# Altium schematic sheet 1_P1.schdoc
size 604 x 431 mm; Symbol: sheet-symbol_a4; Device: Sheet-Symbol_A4; @Page Name: P1; @Create Date: 2023-08-18; @Page Count: 1; @Page No: 1; @Project Name: 【废土科技】带抬头显示及监控器的多功能观测仪_V3; @Schematic Name: 中控板; @Update Date: 2023-08-20; Company: 嘉立创EDA; Drawed: Kevin_Wuu; Page Size: A4; Version: V1.0
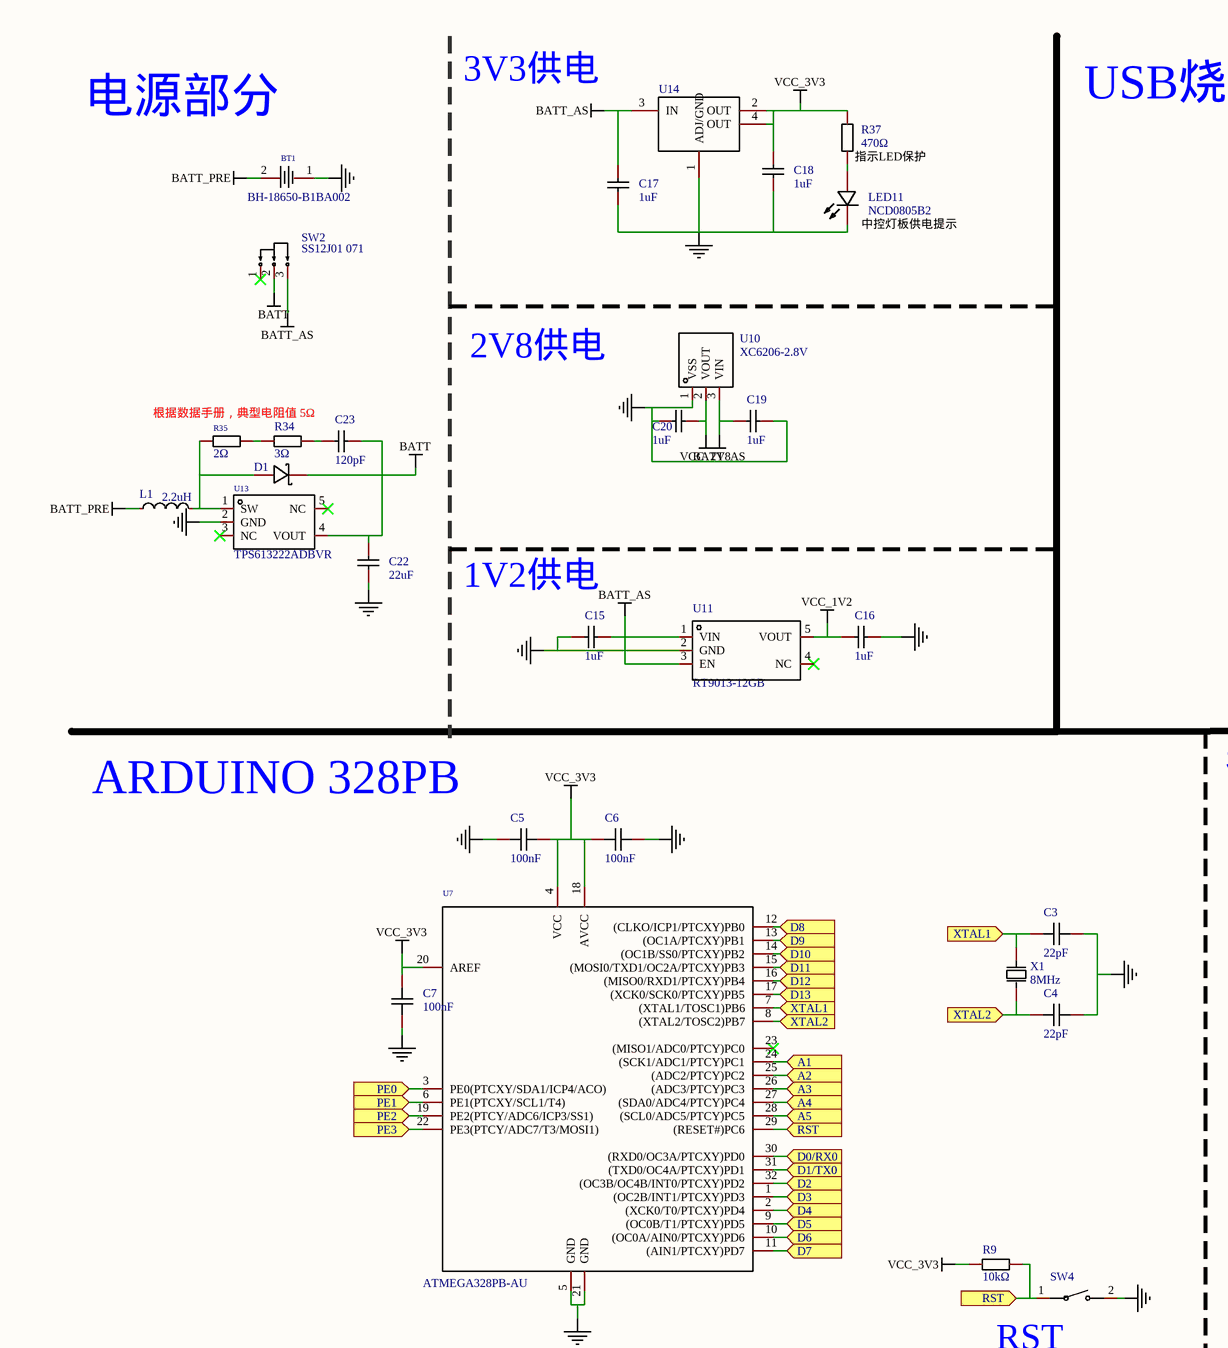
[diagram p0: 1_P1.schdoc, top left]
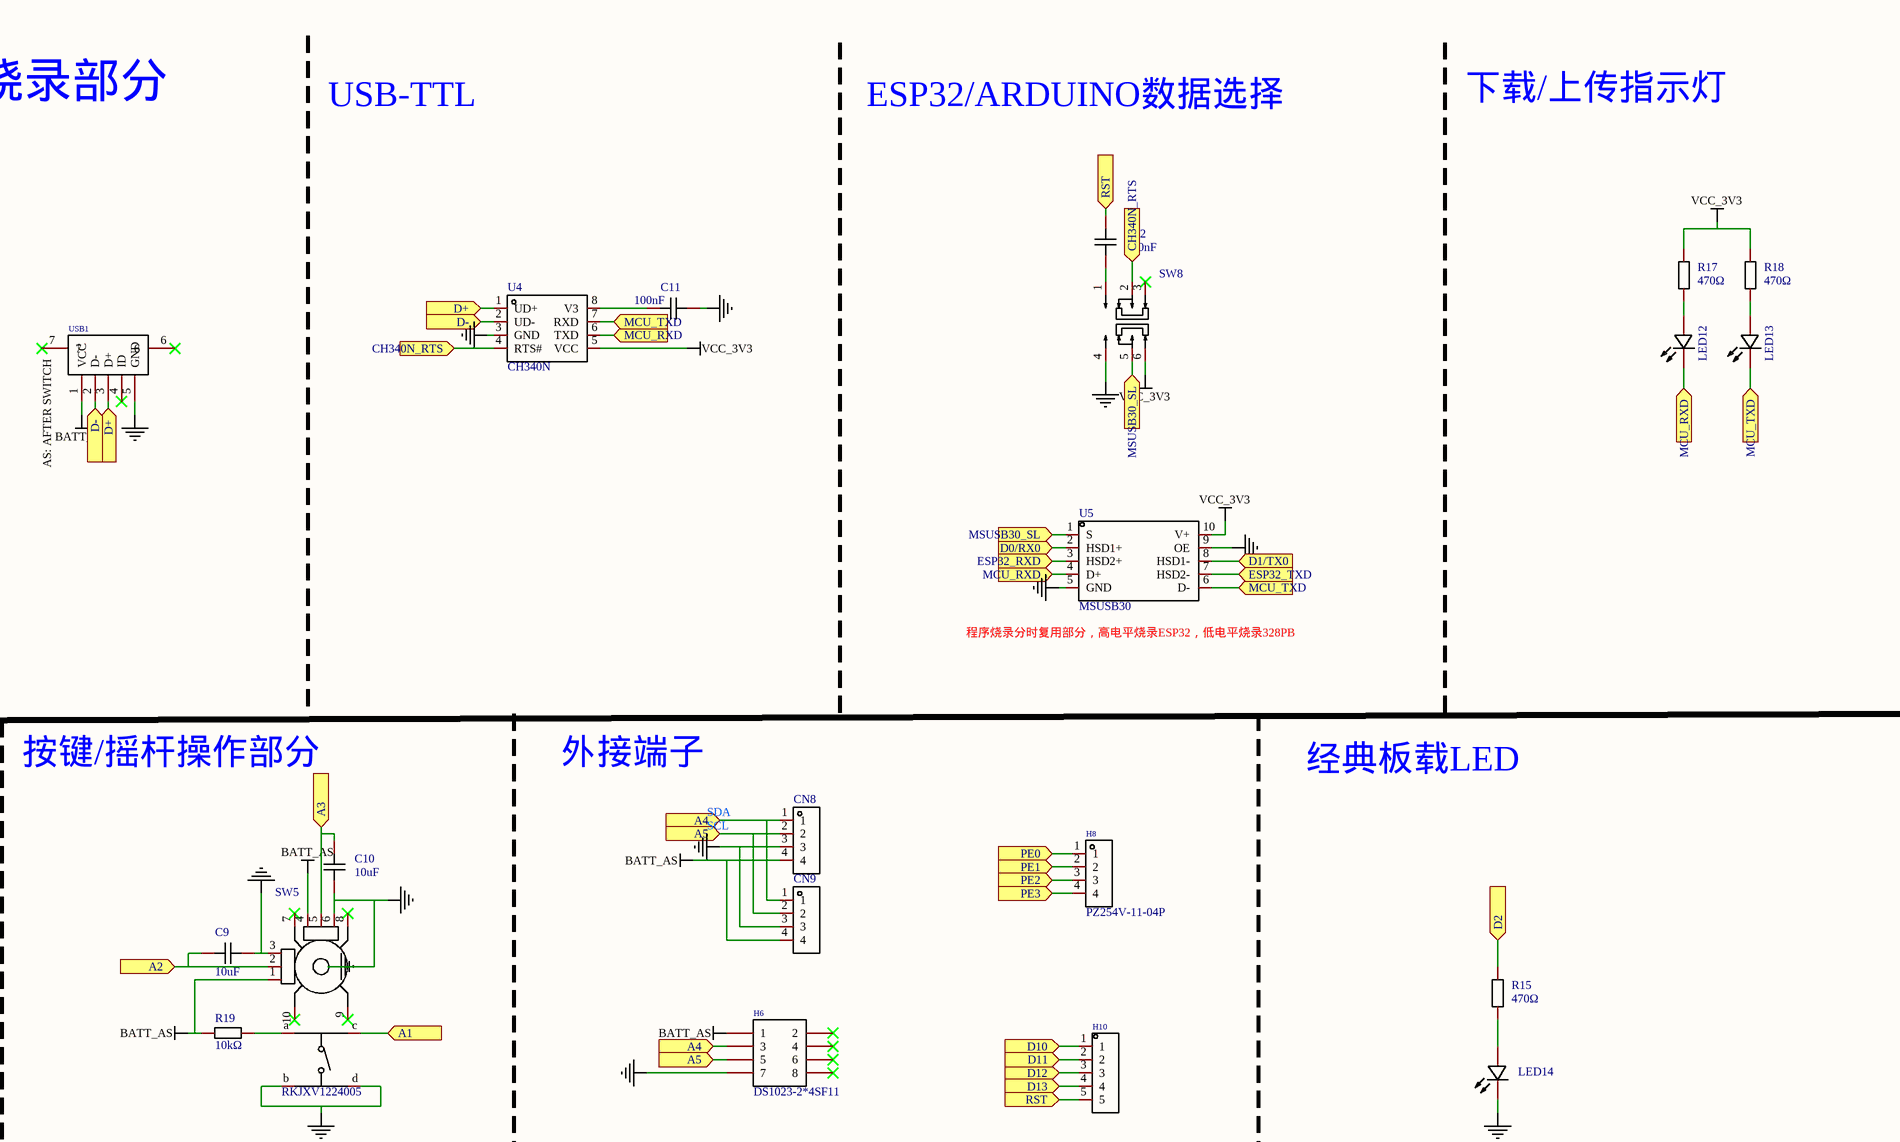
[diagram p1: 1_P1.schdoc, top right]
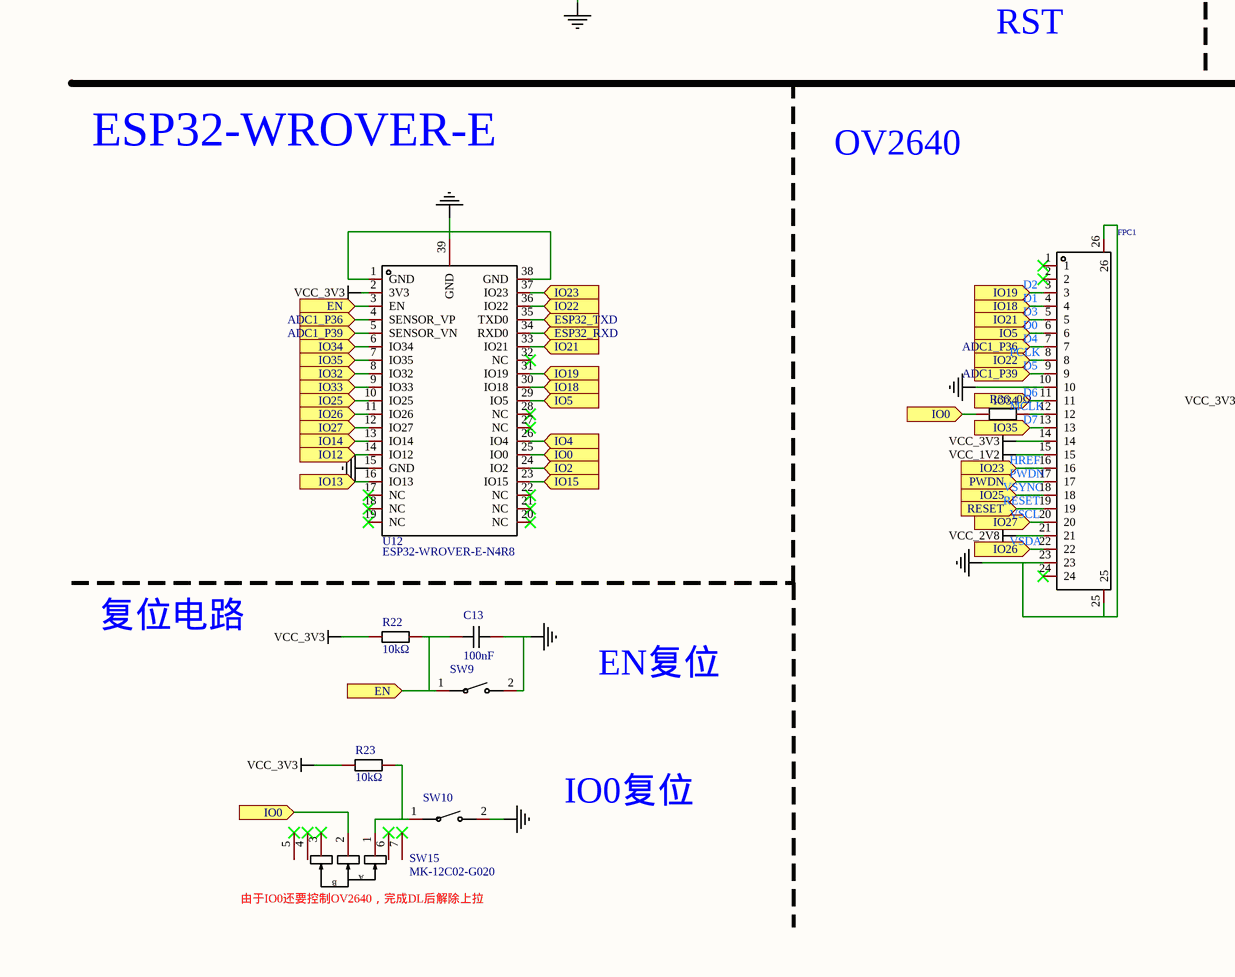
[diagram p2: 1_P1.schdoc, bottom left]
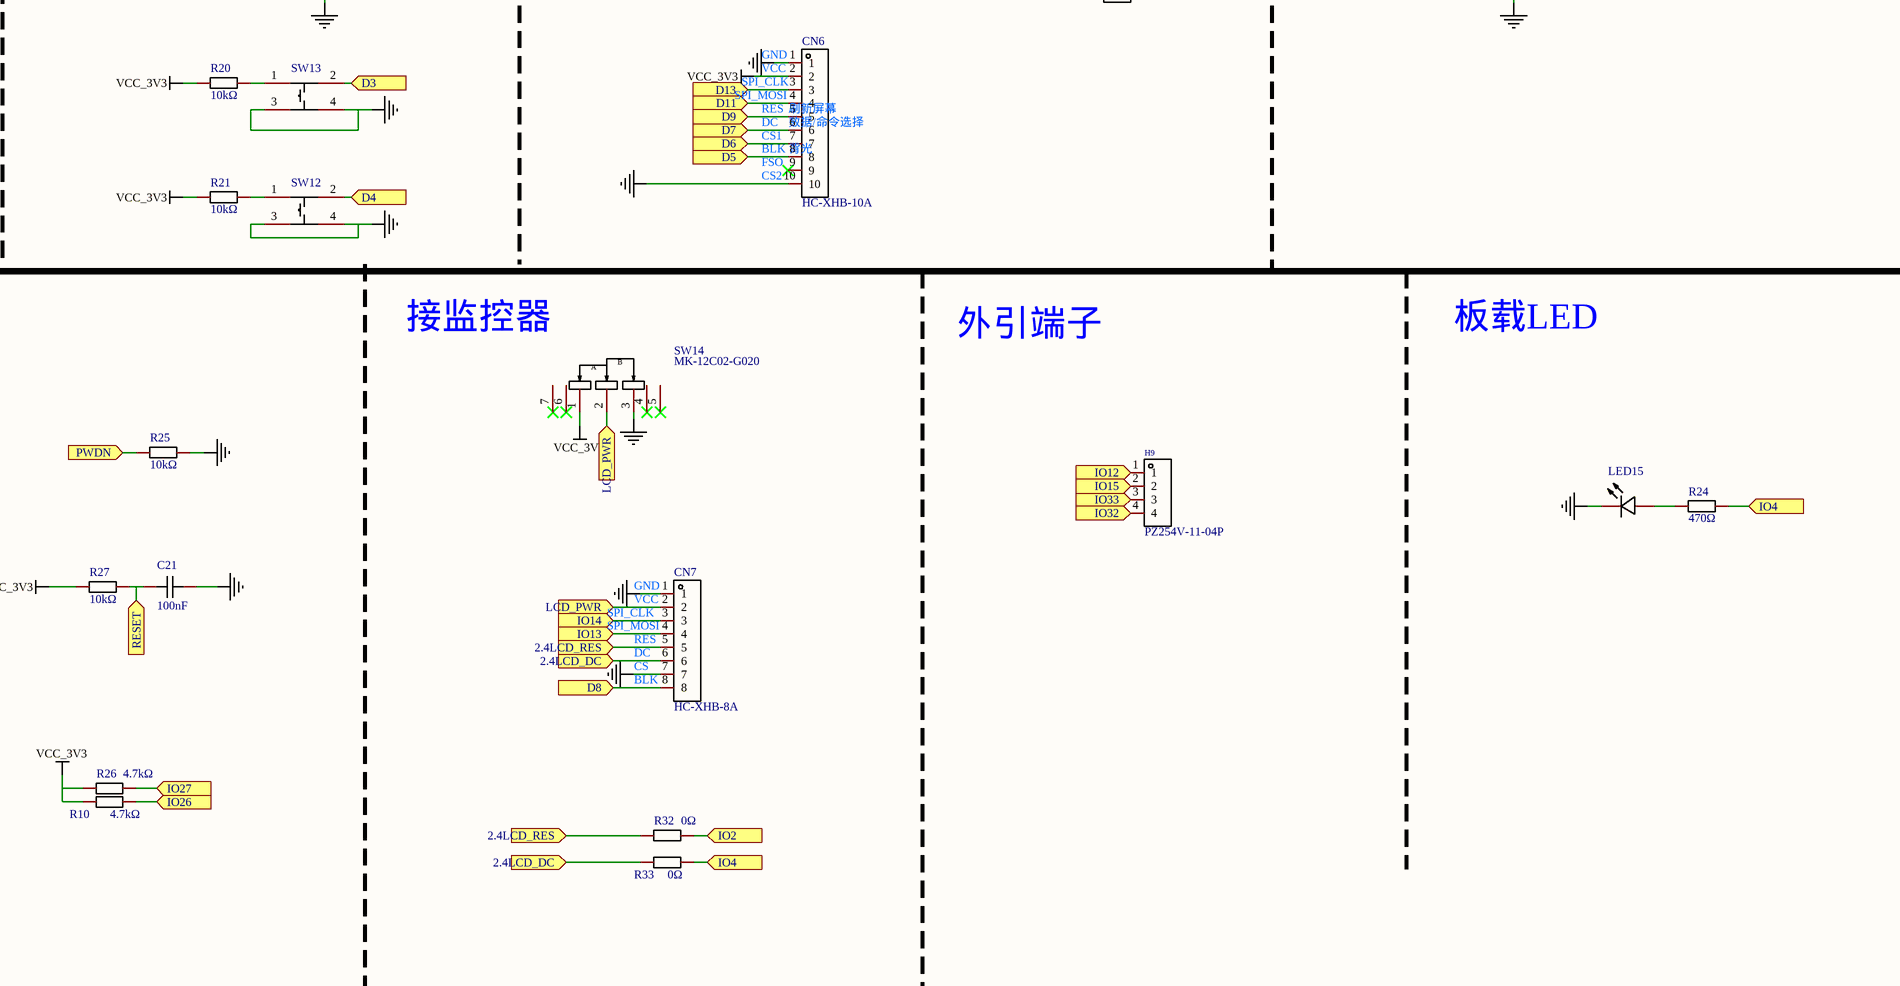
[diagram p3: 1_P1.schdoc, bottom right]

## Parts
BT1  BH-18650-B1BA002  [BATTERY-SMD_18650-1S-L77.1-W20.7-1]
C3  22pF  [C0805]
C4  22pF  [C0805]
C5  100nF  [C0603]
C6  100nF  [C0603]
C7  100nF  [C0603]
C9  10uF  [C0603]
C10  10uF  [C0603]
C11  100nF  [C0603]
C12  100nF  [C0603]
C13  100nF  [C0603]
C15  1uF  [C0805]
C16  1uF  [C0805]
C17  1uF  [C0805]
C18  1uF  [C0805]
C19  1uF  [C0805]
C20  1uF  [C0805]
C21  100nF  [C0603]
C22  22uF  [C1206]
C23  120pF  [C0603]
CN6  HC-XHB-10A  [CONN-TH_10P-P2.50_HCTL_HC-XHB-10A]
CN7  HC-XHB-8A  [CONN-TH_8P-P2.50_HCTL_HC-XHB-8A]
CN8  HX25035-4A  [CONN-TH_4P-P2.50_HX25035-4A]  (value not drawn)
CN9  HX25035-4A  [CONN-TH_4P-P2.50_HX25035-4A]  (value not drawn)
D1  MSK240AW  [SOD-123FL_L2.8-W1.8-LS3.7-RD]  (value not drawn)
FPC1  AFC24-S24FIA-00  [FPC-SMD_P0.50-24P_QCHF-SM-H2.0]  (value not drawn)
H6  DS1023-2*4SF11  [HDR-TH_8P-P2.54-V-F-R2-C4-S2.54-1]
H8  PZ254V-11-04P  [HDR-TH_4P-P2.54-V-M]
H9  PZ254V-11-04P  [HDR-TH_4P-P2.54-V-M]
H10  HDR-M_2.54_1x5P  [HDR-TH_5P-P2.54-V-M]  (value not drawn)
L1  2.2uH  [IND-SMD_L4.4-W4.2]
LED11  NCD0805B2  [LED0805-R-RD]
LED12  NCD0603R5  [LED0603-RD]  (value not drawn)
LED13  NCD0603R5  [LED0603-RD]  (value not drawn)
LED14  NCD0603R5  [LED0603-RD]  (value not drawn)
LED15  NCD0603R5  [LED0603-RD]  (value not drawn)
R9  10kΩ  [R0805]
R10  4.7kΩ  [R0805]
R15  470Ω  [R0603]
R17  470Ω  [R0603]
R18  470Ω  [R0603]
R19  10kΩ  [R0805]
R20  10kΩ  [R0805]
R21  10kΩ  [R0805]
R22  10kΩ  [R0805]
R23  10kΩ  [R0805]
R24  470Ω  [R0603]
R25  10kΩ  [R0805]
R26  4.7kΩ  [R0805]
R27  10kΩ  [R0805]
R32  0Ω  [R0603]
R33  0Ω  [R0603]
R34  3Ω  [R0603]
R35  2Ω  [R0603]
R36  0Ω  [R0603]
R37  470Ω  [R0603]
SW2  SS12J01 071  [SW-TH_SHOU-HAN_SS12J01]
SW4  K2-1107ST-A4DW-06  [KEY-SMD_L6.2-W3.6-LS8.0]  (value not drawn)
SW5  RKJXV1224005  [SW-TH_RKJXV1224005]
SW8  MS-22D28-G020  [SW-SMD_MS-22D28-G020]  (value not drawn)
SW9  K2-1107ST-A4DW-06  [KEY-SMD_L6.2-W3.6-LS8.0]  (value not drawn)
SW10  K2-1107ST-A4DW-06  [KEY-SMD_L6.2-W3.6-LS8.0]  (value not drawn)
SW12  TS-1009S-03826  [SW-SMD_4P-L4.5-W4.5-P3.00-LS7.0]  (value not drawn)
SW13  TS-1009S-03826  [SW-SMD_4P-L4.5-W4.5-P3.00-LS7.0]  (value not drawn)
SW14  MK-12C02-G020  [SW-SMD_MK-12C02-G020]
SW15  MK-12C02-G020  [SW-SMD_MK-12C02-G020]
U4  CH340N  [SOP-8_L4.9-W3.9-P1.27-LS6.0-BL]
U5  MSUSB30  [MSOP-10_L3.0-W3.0-P0.50-LS5.0-BL]
U7  ATMEGA328PB-AU  [TQFP-32_L7.0-W7.0-P0.80-LS9.0-BL]
U10  XC6206-2.8V  [SOT-23-3_L2.9-W1.6-P1.90-LS2.8-BR]
U11  RT9013-12GB  [SOT-23-5_L3.0-W1.7-P0.95-LS2.8-BR]
U12  ESP32-WROVER-E-N4R8  [WIFI-SMD_ESP32-WROVER-E]
U13  TPS613222ADBVR  [TSOT-23-5_L2.9-W1.6-P0.95-LS2.8-BR]
U14  TLV1117LV33DCYR  [SOT-223_L6.7-W3.5-P2.30-BR]  (value not drawn)
USB1  920-462A2021Y10102  [MINI-USB-TH_C13453]  (value not drawn)
X1  8MHz  [OSC-TH_L10.0-W4.5-P5.00]

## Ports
2.4LCD_DC (in), 2.4LCD_RES (in), A1 (in), A2 (in), A3 (in), A4 (in), A5 (in), ADC1_P36 (in), ADC1_P39 (in), CH340N_RTS (in), D0/RX0 (in), D1/TX0 (in), D2 (in), D3 (in), D4 (in), D5 (in), D6 (in), D7 (in), D8 (in), D9 (in), D10 (in), D11 (in), D12 (in), D13 (in), D+ (in), D- (in), EN (in), ESP32_RXD (in), ESP32_TXD (in), IO0 (in), IO2 (in), IO4 (in), IO5 (in), IO12 (in), IO13 (in), IO14 (in), IO15 (in), IO18 (in), IO19 (in), IO21 (in), IO22 (in), IO23 (in), IO25 (in), IO26 (in), IO27 (in), IO32 (in), IO33 (in), IO34 (in), IO35 (in), LCD_PWR (in), MCU_RXD (in), MCU_TXD (in), MSUSB30_SL (in), PE0 (in), PE1 (in), PE2 (in), PE3 (in), PWDN (in), RESET (in), RST (in), XTAL1 (in), XTAL2 (in)

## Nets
BATT: C22.2 C23.2 D1.1(K) SW2.2 U13.4(VOUT)
BATT_AS: C15.2 C17.1 C19.1 CN8.4 CN9.4 H6.1 R19.2 SW2.3 SW5.1(B) SW5.4(A) U10.3(VIN) U11.1(VIN) U11.3(EN) U14.3(IN) USB1.1(VCC)
BATT_PRE: BT1.2 L1.1
NetBT1_1: BT1.1 C3.1 C4.1 C5.1 C6.2 C7.1 C9.2 C10.1 C11.2 C13.2 C15.1 C16.1 C17.2 C18.2 C19.2 C20.2 C21.1 C22.1 CN6.1 CN6.10 CN7.1 CN7.7 CN8.3 CN9.3 FPC1.10 FPC1.23 FPC1.25 FPC1.26 H6.7 LED11.2(-) LED14.1(-) LED15.1(-) R25.1 SW4.2 SW5.3(A) SW5.6(B) SW5.b SW5.d SW8.4 SW9.2 SW10.2 SW12.3 SW12.4 SW13.3 SW13.4 SW14.3 U4.3(GND) U5.5(GND) U5.9(OE) U7.5(GND) U7.21(GND) U10.1(VSS) U11.2(GND) U12.1(GND) U12.15(GND) U12.38(GND) U12.39(GND) U13.2(GND) U14.1(ADJ/GND) USB1.5(GND)
VCC_1V2: C16.2 FPC1.15 U11.5(VOUT)
VCC_2V8: C20.1 FPC1.21 U10.2(VOUT)
VCC_3V3: C5.2 C6.1 C7.2 C18.1 CN6.2 FPC1.14 R9.2 R10.2 R17.2 R18.2 R20.2 R21.2 R22.2 R23.2 R26.2 R27.2 R37.2 SW8.6 SW14.1 U4.5(VCC) U5.10(V+) U7.4(VCC) U7.18(AVCC) U7.20(AREF) U12.2(3V3) U14.2(OUT) U14.4(OUT)
2.4LCD_DC: CN7.6 R33.1 ; port 2.4LCD_DC
2.4LCD_RES: CN7.5 R32.1 ; port 2.4LCD_RES
A1: SW5.c U7.24((SCK1/ADC1/PTCY)PC1) ; port A1
A2: C9.1 SW5.2(DTA) U7.25((ADC2/PTCY)PC2) ; port A2
A3: C10.2 SW5.5(DTA) U7.26((ADC3/PTCY)PC3) ; port A3
A4: CN8.1 CN9.1 H6.3 U7.27((SDA0/ADC4/PTCY)PC4) ; port A4
A5: CN8.2 CN9.2 H6.5 U7.28((SCL0/ADC5/PTCY)PC5) ; port A5
ADC1_P36: FPC1.7 U12.4(SENSOR_VP) ; port ADC1_P36
ADC1_P39: FPC1.9 U12.5(SENSOR_VN) ; port ADC1_P39
CH340N_RTS: SW8.2 U4.4(RTS#) ; port CH340N_RTS
D0/RX0: U5.2(HSD1+) U7.30((RXD0/OC3A/PTCXY)PD0) ; port D0/RX0
D1/TX0: U5.8(HSD1-) U7.31((TXD0/OC4A/PTCXY)PD1) ; port D1/TX0
D2: R15.2 U7.32((OC3B/OC4B/INT0/PTCXY)PD2) ; port D2
D3: SW13.2 U7.1((OC2B/INT1/PTCXY)PD3) ; port D3
D4: SW12.2 U7.2((XCK0/T0/PTCXY)PD4) ; port D4
D5: CN6.8 U7.9((OC0B/T1/PTCXY)PD5) ; port D5
D6: CN6.7 U7.10((OC0A/AIN0/PTCXY)PD6) ; port D6
D7: CN6.6 U7.11((AIN1/PTCXY)PD7) ; port D7
D8: CN7.8 U7.12((CLKO/ICP1/PTCXY)PB0) ; port D8
D9: CN6.5 U7.13((OC1A/PTCXY)PB1) ; port D9
D10: H10.1 U7.14((OC1B/SS0/PTCXY)PB2) ; port D10
D11: CN6.4 H10.2 U7.15((MOSI0/TXD1/OC2A/PTCXY)PB3) ; port D11
D12: H10.3 U7.16((MISO0/RXD1/PTCXY)PB4) ; port D12
D13: CN6.3 H10.4 U7.17((XCK0/SCK0/PTCXY)PB5) ; port D13
D+: U4.1(UD+) USB1.3(D+) ; port D+
D-: U4.2(UD-) USB1.2(D-) ; port D-
EN: C13.1 R22.1 SW9.1 U12.3(EN) ; port EN
ESP32_RXD: U5.3(HSD2+) U12.34(RXD0) ; port ESP32_RXD
ESP32_TXD: U5.7(HSD2-) U12.35(TXD0) ; port ESP32_TXD
IO0: R36.1 SW15.2 U12.25(IO0) ; port IO0
IO2: R32.2 U12.24(IO2) ; port IO2
IO4: R24.2 R33.2 U12.26(IO4) ; port IO4
IO5: FPC1.6 U12.29(IO5) ; port IO5
IO12: H9.1 U12.14(IO12) ; port IO12
IO13: CN7.4 U12.16(IO13) ; port IO13
IO14: CN7.3 U12.13(IO14) ; port IO14
IO15: H9.2 U12.23(IO15) ; port IO15
IO18: FPC1.4 U12.30(IO18) ; port IO18
IO19: FPC1.3 U12.31(IO19) ; port IO19
IO21: FPC1.5 U12.33(IO21) ; port IO21
IO22: FPC1.8 U12.36(IO22) ; port IO22
IO23: FPC1.16 U12.37(IO23) ; port IO23
IO25: FPC1.18 U12.10(IO25) ; port IO25
IO26: FPC1.22 R10.1 U12.11(IO26) ; port IO26
IO27: FPC1.20 R26.1 U12.12(IO27) ; port IO27
IO32: H9.4 U12.8(IO32) ; port IO32
IO33: H9.3 U12.9(IO33) ; port IO33
IO34: FPC1.11 U12.6(IO34) ; port IO34
IO35: FPC1.13 U12.7(IO35) ; port IO35
LCD_PWR: CN7.2 SW14.2 ; port LCD_PWR
MCU_RXD: LED12.1(-) U4.6(TXD) U5.4(D+) ; port MCU_RXD
MCU_TXD: LED13.1(-) U4.7(RXD) U5.6(D-) ; port MCU_TXD
MSUSB30_SL: SW8.5 U5.1(S) ; port MSUSB30_SL
PE0: H8.1 U7.3(PE0(PTCXY/SDA1/ICP4/ACO)) ; port PE0
PE1: H8.2 U7.6(PE1(PTCXY/SCL1/T4)) ; port PE1
PE2: H8.3 U7.19(PE2(PTCY/ADC6/ICP3/SS1)) ; port PE2
PE3: H8.4 U7.22(PE3(PTCY/ADC7/T3/MOSI1)) ; port PE3
PWDN: FPC1.17 R25.2 ; port PWDN
RESET: C21.2 FPC1.19 R27.1 ; port RESET
RST: C12.2 H10.5 R9.1 SW4.1 U7.29((RESET#)PC6) ; port RST
XTAL1: C3.2 U7.7((XTAL1/TOSC1)PB6) X1.1(OSC1) ; port XTAL1
XTAL2: C4.2 U7.8((XTAL2/TOSC2)PB7) X1.2(OSC2) ; port XTAL2
NetC11_1: C11.1 U4.8(V3)
NetC12_1: C12.1 SW8.1
NetC23_1: C23.1 R34.2
NetD1_2: D1.2(A) L1.2 R35.1 U13.1(SW)
NetFPC1_12: FPC1.12 R36.2
NetLED11_1: LED11.1(+) R37.1
NetLED12_2: LED12.2(+) R17.1
NetLED13_2: LED13.2(+) R18.1
NetLED14_2: LED14.2(+) R15.1
NetLED15_2: LED15.2(+) R24.1
NetR19_1: R19.1 SW5.a
NetR20_1: R20.1 SW13.1
NetR21_1: R21.1 SW12.1
NetR23_1: R23.1 SW10.1 SW15.1
NetR34_1: R34.1 R35.2

Not connected (* = marked no-connect by the designer): CN6 9*; FPC1 1* 2* 24*; H6 2* 4* 6* 8*; SW2 1*; SW5 7(GND)* 8(GND)* 9(GND)* 10(GND)*; SW8 3*; SW14 4* 5* 6* 7*; SW15 3* 4* 5* 6* 7*; U7 23((MISO1/ADC0/PTCY)PC0)*; U11 4(NC)*; U12 17(NC)* 18(NC)* 19(NC)* 20(NC)* 21(NC)* 22(NC)* 27(NC)* 28(NC)* 32(NC)*; U13 3(NC)* 5(NC)*; USB1 4(ID)* 6* 7*

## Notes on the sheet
- 3V3供电
- 电源部分
- (near R37) 指示LED保护
- USB烧录部分
- USB-TTL
- ESP32/ARDUINO数据选择
- 下载/上传指示灯
- (near LED11) 中控灯板供电提示
- 2V8供电
- (near R35) 根据数据手册，典型电阻值 5Ω
- (near USB1) AS: AFTER SWITCH
- (near C15) 1V2供电
- (near U5) 程序烧录分时复用部分，高电平烧录ESP32，低电平烧录328PB
- ARDUINO 328PB
- 按键/摇杆操作部分
- 外接端子
- SCL
- SDA
- 经典板载LED
- (near CN6) SPI_MOSI
- (near CN6) SPI_CLK
- (near CN6) GND
- (near CN6) VCC
- (near CN6) RES
- (near CN6) 刷新屏幕
- (near CN6) DC
- (near CN6) CS1
- (near CN6) BLK
- (near CN6) FSO
- (near CN6) CS2
- (near CN6) 数据/命令选择
- (near CN6) 背光
- (near SW4) RST
- ESP32-WROVER-E
- OV2640
- 接监控器
- 外引端子
- 板载LED
- (near FPC1) D2
- (near FPC1) D1
- (near FPC1) D3
- (near FPC1) D0
- (near FPC1) PCLK
- (near FPC1) D4
- (near FPC1) D5
- D6
- (near R36) MCLK
- (near FPC1) HREF
- (near R36) D7
- (near CN7) SPI_CLK
- (near CN7) SPI_MOSI
- (near CN7) GND
- (near CN7) VCC
- (near CN7) RES
- (near CN7) DC
- (near FPC1) VSYNC
- (near FPC1) RESET
- (near FPC1) PWDN
- (near FPC1) VSCL
- (near CN7) BLK
- (near CN7) CS
- (near FPC1) VSDA
- 复位电路
- EN复位
- IO0复位
- (near SW15) 由于IO0还要控制OV2640，完成DL后解除上拉

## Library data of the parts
BT1 = BH-18650-B1BA002: 连接器类型:电池盒;适用电池规格:18650;; Manufacturer: MYOUNG(美阳); Add into BOM: yes; Connector Type: 电池盒; Battery Type: 18650
C3 C4 = 0805CG220F500NT: 容值:22pF;精度:±1%;额定电压:50V;材质(温度系数):C0G;; Manufacturer: FH(风华); Add into BOM: yes; Tolerance: ±1%; Voltage Rated: 50V; Temperature Coefficient: C0G
C5-C7 C11-C13 C21 = CC0603KRX7R9BB104: 容值:100nF;精度:±10%;额定电压:50V;材质(温度系数):X7R;; Manufacturer: YAGEO(国巨); Add into BOM: yes; Tolerance: ±10%; Voltage Rated: 50V; Temperature Coefficient: X7R
C9 C10 = GRM188R61E106KA73D: 容值:10uF;精度:±10%;额定电压:25V;材质(温度系数):X5R;; Manufacturer: muRata(村田); Add into BOM: yes; Tolerance: ±10%; Voltage Rated: 25V; Temperature Coefficient: X5R
C15-C20 = CL21B105KBFNNNE: 容值:1uF;精度:±10%;额定电压:50V;材质(温度系数):X7R;; Manufacturer: SAMSUNG(三星); Add into BOM: yes; Tolerance: ±10%; Voltage Rated: 50V; Temperature Coefficient: X7R
C22 = CL31A226KAHNNNE: 容值:22uF;精度:±10%;额定电压:25V;材质(温度系数):X5R;; Manufacturer: SAMSUNG(三星); Add into BOM: yes; Tolerance: ±10%; Voltage Rated: 25V; Temperature Coefficient: X5R
C23 = CC0603JRNPO9BN121: 容值:120pF;精度:±5%;额定电压:50V;材质(温度系数):NP0;; Manufacturer: YAGEO(国巨); Add into BOM: yes; Tolerance: ±5%; Voltage Rated: 50V; Temperature Coefficient: NP0
CN6 = HC-XHB-10A: 参考系列:-;间距:2.5mm;插针结构:1x10P;排数:1;每排PIN数:10;行距:-;公母:公型插针;安装方式:直插;额定电流:3A;工作温度范围:-25℃~+85℃;; Manufacturer: HCTL(华灿天禄); Add into BOM: yes; Pitch: 2.5mm; Pins Structure: 1x10P; Number of PINs Per Row: 10; Gender: 公型插针; Current Rating (Max): 3A
CN7 = HC-XHB-8A: 参考系列:-;间距:2.5mm;插针结构:1x8P;排数:1;每排PIN数:8;行距:-;公母:公型插针;安装方式:直插;额定电流:3A;工作温度范围:-25℃~+85℃;; Manufacturer: HCTL(华灿天禄); Add into BOM: yes; Pitch: 2.5mm; Pins Structure: 1x8P; Number of PINs Per Row: 8; Gender: 公型插针; Current Rating (Max): 3A
CN8 CN9 = HX25035-4A: 参考系列:-;间距:2.5mm;插针结构:1x4P;排数:1;每排PIN数:4;行距:-;公母:公型插针;安装方式:直插;额定电流:-;工作温度范围:-;; Manufacturer: HX(红星); Add into BOM: yes; Pitch: 2.5mm; Pins Structure: 1x4P; Number of PINs Per Row: 4; Gender: 公型插针
D1 = MSK240AW: Manufacturer: SHIKUES(时科); Add into BOM: yes
FPC1 = AFC24-S24FIA-00: 间距:0.5mm;触点数量:24P;锁定特性:翻盖式;安装类型:卧贴;触点类型:双侧触点/上下接;; Manufacturer: JS(钜硕电子); Add into BOM: yes; Pitch: 0.5mm; Number of Contacts: 24P; Locking Feature: 翻盖式; FFC, FCB Thickness: 0.3mm
H6 = DS1023-2*4SF11: 排数:双排;总孔位数:8;间距:2.54mm;插孔结构:2x4P;行距:2.54mm;安装类型:直插;塑高:-;触头材质:-;触头镀层:-;; Manufacturer: CONNFLY; Add into BOM: yes; Number of Holes: 8; Pitch: 2.54mm; Holes Structure: 2x4P
H8 H9 = PZ254V-11-04P: 排数:单排;总PIN位数:4P;间距:2.54mm;插针结构:1x4P;行距:-;安装类型:直插;圆针/方针:方针;额定电流:3A;额定电压:250V;配合针长度:6mm;塑高:2.5mm;端接针长度:3mm;触头材质:-;工作温度范围:-40℃~+105℃;颜色:黑色;; Manufacturer: XFCN(兴飞); Symbol: PZ254V-11-04P_C2691448; Add into BOM: yes; Pitch: 2.54mm; Pin Structure: 1x4P; Circluar Pins/Square Pins: 方针; Current Rating (Max): 3A; Voltage Rating (Max): 250V
H10 = HDR-M_2.54_1x5P: Manufacturer: MINTRON(明硕); Symbol: MTP125-1105S1; Convert to PCB: yes
L1 = MWSA0402S-2R2MT: 电感值:2.2uH;精度:±20%;额定电流:4.5A;直流电阻(DCR):58mΩ;; Manufacturer: Sunlord(顺络); Add into BOM: yes; Tolerance: ±20%; Rated Current: 4.5A; DC Resistance (DCR): 58mΩ
LED11 = NCD0805B2: 发光颜色:蓝灯;; Manufacturer: 国星光电; Symbol: FC-A2012BK-470H2; Add into BOM: yes; Emitted Color: 蓝灯
LED12-LED15 = NCD0603R5: 发光颜色:红灯;二极管配置:-;主波长:620nm;色温:-;功率:65mW;安装方式:-;; Manufacturer: 国星光电; Add into BOM: yes; Emitted Color: 红灯; Dominant Wavelength: 620nm; Peak Wavelength: 630nm; Forward Current: 20mA; Power Dissipation: 65mW; Viewing Angle: 130°
R9 R19-R23 R25 R27 = RMCF0805FT10K0: 电阻类型:厚膜电阻;阻值:10kΩ;精度:±1%;功率:125mW;; Manufacturer: SEI(Stackpole Electronics Inc.); Add into BOM: yes; Tolerance: ±1%; Power(Watts): 125mW; Temperature Coefficient: ±100ppm/℃; Overload Voltage (Max): 150V
R10 R26 = 0805W8F4701T5E: 电阻类型:厚膜电阻;阻值:4.7kΩ;精度:±1%;功率:125mW;; Manufacturer: UNI-ROYAL(厚声); Add into BOM: yes; Tolerance: ±1%; Power(Watts): 125mW; Temperature Coefficient: ±100ppm/℃; Overload Voltage (Max): 150V
R15 R17 R18 R24 R37 = 0603WAF4700T5E: 电阻类型:厚膜电阻;阻值:470Ω;精度:±1%;功率:100mW;; Manufacturer: UNI-ROYAL(厚声); Add into BOM: yes; Tolerance: ±1%; Power(Watts): 100mW; Temperature Coefficient: ±100ppm/℃; Overload Voltage (Max): 75V
R32 R33 R36 = 0603WAF0000T5E: 电阻类型:厚膜电阻;阻值:0Ω;精度:±1%;功率:100mW;; Manufacturer: UNI-ROYAL(厚声); Add into BOM: yes; Tolerance: ±1%; Power(Watts): 100mW; Overload Voltage (Max): 75V
R34 = RC0603FR-073RL: 电阻类型:厚膜电阻;阻值:3Ω;精度:±1%;功率:100mW;; Manufacturer: YAGEO(国巨); Add into BOM: yes; Tolerance: ±1%; Power(Watts): 100mW; Temperature Coefficient: ±200ppm/℃; Overload Voltage (Max): 75V
R35 = 0603WAF200KT5E: 电阻类型:厚膜电阻;阻值:2Ω;精度:±1%;功率:100mW;温度系数:±200ppm/℃;; Manufacturer: UNI-ROYAL(厚声); Add into BOM: yes; Tolerance: ±1%; Power(Watts): 100mW; Overload Voltage (Max): 75V
SW2 = SS12J01 071: 额定电流(DC):3A;额定电压(DC):250V;额定电流(AC):-;额定电压(AC):-;电路结构:单刀双掷;安装方式:立插;机械寿命:3千次;开关颜色:-;; Manufacturer: SHOU HAN(首韩); Add into BOM: yes; Current Rating (DC): 3A; Voltage Rating (DC): 250V; Circuit: 单刀双掷; Mechanical Life: 3千次; Pin Style: PC引脚; Switch Length: 19.8mm; Switch Width: 10mm; Switch Height: 6.2mm; Check: true
SW4 SW9 SW10 = K2-1107ST-A4DW-06_C118141: 触点电流:50mA;额定电压(DC):12V;绝缘电阻:100MΩ;电路结构:单刀单掷;安装方式:立贴;按钮形状:矩形按钮;带灯:-;作用力:250gf@±30gf;机械寿命:100000;工作温度:-25℃~+85℃;开关长度:6.1mm;开关宽度:3.6mm;开关高度:2.5mm;; Manufacturer: 韩国韩荣; Symbol: K2-1107ST-A4SW-06; Add into BOM: yes; Contact Current: 50mA; Voltage Rating (DC): 12V; Insulation Resistance: 100MΩ; Circuit: 单刀单掷; Actuator Style: 矩形按钮; Mechanical Life: 100000; Switch Length: 6.1mm; Switch Width: 3.6mm; Switch Height: 2.5mm
SW5 = RKJXV1224005: 操纵杆复位 中央按动开关 适用于航模玩具遥控器电位器、3D摇杆PS4手柄游戏机、无人机摇杆电位器、工业控制器; Manufacturer: ALPSALPINE(阿尔卑斯阿尔派); Add into BOM: yes; Check: true
SW8 = MS-22D28-G020: 立贴六脚三挡微型拨动开关; Manufacturer: G-Switch(品赞); Add into BOM: yes
SW12 SW13 = TS-1009S-03826: 触点电流:50mA;额定电压(DC):12V;电路结构:单刀单掷;安装方式:立贴;带灯:-;机械寿命:-;; Manufacturer: XUNPU(讯普); Add into BOM: yes; Contact Current: 50mA; Voltage Rating (DC): 12V; Circuit: 单刀单掷; Actuator Style: 圆形按钮; Switch Length: 4.5mm; Switch Height: 3.8mm
SW14 SW15 = MK-12C02-G020: 七脚小拨动开关G2.0; Manufacturer: G-Switch(品赞); Add into BOM: yes
U4 = CH340N: Manufacturer: WCH(南京沁恒); Symbol: CH340N_C2977777; Add into BOM: yes
U5 = MSUSB30: 开关电路:-;多路复用器/解复用器电路:-;导通电阻（最大值）:-;开关电压（最大值）:-;; Manufacturer: 杭州瑞盟; Add into BOM: yes
U7 = ATMEGA328PB-AU: CPU内核:AVR;CPU最大主频:20MHz;工作电压范围:1.8V~5.5V;程序存储容量:32KB;程序存储器类型:FLASH;RAM总容量:2KB;GPIO端口数量:27;; Manufacturer: MICROCHIP(美国微芯); Add into BOM: yes; CPU Core: AVR; CPU Maximum Speed: 20MHz; Program Storage Size: 32KB; Program Memory Type: FLASH; RAM Size: 2KB; GPIO Ports Number: 27; ADC (Bit): 10bit; Watchdog: 有
U10 = XC6206-2.8V: 输出类型:固定;输出极性:正;最大输入电压:6V;输出电压:2.8V;输出电流:250mA;; Manufacturer: YONGYUTAI(永裕泰); Add into BOM: yes; Output Type: 固定; Output Polarity: 正; Number of Outputs: 1; Maximum Input Voltage: 6V; Output Voltage: 2.8V; Output Current: 250mA
U11 = RT9013-12GB: 输出类型:固定;输出极性:正;最大输入电压:5.5V;输出电压:1.2V~1.2V;输出电流:500mA;电源纹波抑制比(PSRR):50dB@(10kHz);; Manufacturer: RICHTEK(立锜); Add into BOM: yes; Output Type: 固定; Output Polarity: 正; Number of Outputs: 1; Maximum Input Voltage: 5.5V; Dropout Voltage: 400mV@(500mA); Output Current: 500mA
U12 = ESP32-WROVER-E-N4R8: Manufacturer: ESPRESSIF(乐鑫); Add into BOM: yes
U13 = TPS613222ADBVR: 功能类型:升压型;输出类型:固定;输入电压:900mV~5.5V;输出电压:5V;输出电流(最大值):2.5A;; Manufacturer: TI(德州仪器); Add into BOM: yes; Function: 升压型; Synchronous Rectification: 是; Output Type: 固定; Number of Outputs: 1; Topology: 升压式; Output Voltage: 5V; Output Current (Max): 2.5A; Switching Frequency: 2MHz
U14 = TLV1117LV33DCYR: 输出类型:固定;输出极性:正;最大输入电压:5.5V;输出电压:3.3V;输出电流:1A;电源纹波抑制比(PSRR):75dB@(120Hz);; Manufacturer: TI(德州仪器); Add into BOM: yes; Output Type: 固定; Output Polarity: 正; Number of Outputs: 1; Maximum Input Voltage: 5.5V; Output Voltage: 3.3V; Dropout Voltage: 1.3V@(800mA); Output Current: 1A
USB1 = 920-462A2021Y10102: 连接器类型:Mini-B;标准:USB 2.0;公母:母座;触点数量:5;端口数量:1;; Manufacturer: 精拓金; Symbol: USB-MINI-6.9X10.H-H3.9-DIP-V; Add into BOM: yes; Connector Type: Mini-B; Gender: 母座; Number of Contacts: 5; Number of Ports: 1
X1 = X49SD8MSD2SC: 频率:8MHz;频率公差:±20ppm;负载电容:20pF;; Manufacturer: YXC(扬兴晶振); Add into BOM: yes; Crystal Type: 49S晶振; Frequency Tolerance: ±20ppm; Frequency Stability: ±30ppm; Load Capacitance: 20pF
